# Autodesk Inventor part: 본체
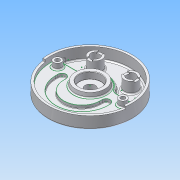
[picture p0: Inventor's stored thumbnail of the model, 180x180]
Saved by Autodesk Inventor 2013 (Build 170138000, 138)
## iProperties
Created: 2015-06
Part Number: 본체
Material: 알루미늄 6061
Document SubType Name: Modeling
Designer: Administrator
Density: 2.71 g/cm^3
Mass: 1340.45 g
Surface Area: 1046.04 cm^2
Volume: 494.633 cm^3
Author: Administrator
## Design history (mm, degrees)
sketch "스케치1"
  geometry: C1 r 95 at (0, 0); 1 further point
  constraints: 1 centre point, 1 coincident
  dimensions: "d0" = 190 diameter of C1
extrude "돌출1" new body sketch "스케치1" distance "d2" = 32.5; taper "d3" = 0 deg
sketch "스케치2"
  geometry: C1 r 95 at (0, 0) reference; C2 r 90 at (0, 0)
  constraints: 1 centre point, 1 coincident
  dimensions: "d4" = 180 diameter of C2
extrude "돌출2" cut sketch "스케치2" distance "d6" = 13; taper "d7" = 0 deg
sketch "스케치3"
  geometry: L1 (-95, 0)-(95, 0); L2 (0, 0)-(-94.075, -13.221); L3 (0, 0)-(94.075, -13.221); C1 r 90 at (0, 0) reference; A1 r 95 centre (0, 0) between (-95, 0) and (95, 0) reference
  constraints: 6 end point, 4 point on circle, 1 horizontal, 1 midpoint
  dimensions: "d8" = 8 deg angle of L1 L2; "d9" = 8 deg angle of L1 L3
extrude "돌출3" cut sketch "스케치3" distance "d10" = 5; taper "d11" = 0 deg
sketch "스케치4"
  geometry: C1 r 95 at (0, 0) reference; C2 r 26 at (0, 0)
  constraints: 1 centre point, 1 coincident
  dimensions: "d12" = 52 diameter of C2
extrude "돌출4" join sketch "스케치4" distance "d14" = 11.5; taper "d15" = -15 deg
sketch "스케치5"
  geometry: C1 r 90 at (0, 0) reference; C2 r 35 at (0, 0)
  constraints: 1 centre point, 1 coincident
  dimensions: "d16" = 70 diameter of C2
extrude "돌출5" join sketch "스케치5" distance "d18" = 10; taper "d19" = -10 deg
hole "구멍1" diameter "d22" = 23; stored, may be unused: countersink angle "d26" = 90 deg, drill point angle "d28" = 118 deg; dims "d20" = 10, "d21" = 10, "d23" = 6, "d24" = 50, "d25" = 15, "d27" = 8
sketch "스케치6"
  geometry: C1 r 35 at (0, 0) reference; C2 r 15 at (-40, 52); C3 r 15 at (40, 52)
  constraints: 2 centre point, 1 equal radius, 1 horizontal alignment
  dimensions: "d29" = 80 distance of C3.centre C2.centre; "d31" = 40 horizontal distance of C1.centre C2.centre; "d32" = 52 vertical distance of C3.centre C1.centre; "d33" = 30 diameter of C2
extrude "돌출6" join sketch "스케치6" stored distance "d34" = 10; taper "d35" = 0 deg
hole "구멍2" diameter "d38" = 20; stored, may be unused: countersink angle "d42" = 90 deg, drill point angle "d44" = 118 deg; dims "d36" = 10, "d37" = 10, "d39" = 6, "d40" = 20, "d41" = 15, "d43" = 8
hole "구멍3" diameter "d47" = 20; stored, may be unused: countersink angle "d51" = 90 deg, drill point angle "d53" = 118 deg; dims "d45" = 10, "d46" = 10, "d48" = 6, "d49" = 20, "d50" = 15, "d52" = 8
sketch "스케치7"
  geometry: L1 (-6, 13.748)-(-6, -13.748); L2 (6, 13.748)-(6, -13.748); L3 (66.252, 6)-(93.748, 6); L4 (93.748, -6)-(66.252, -6); C1 r 10 at (0, 0) reference; C2 r 10 at (80, 0) reference; A1 r 15 centre (0, 0) between (-6, 13.748) and (-6, -13.748) reference; A2 r 15 centre (80, 0) between (66.252, 6) and (93.748, 6) reference; 1 further point
  constraints: 8 end point, 8 point on circle, 2 parallel, 1 perpendicular, 1 vertical
  dimensions: "d54" = 12 distance between parallel lines of L2 L1; "d55" = 6 distance from line of C1.centre L1; "d56" = 12 distance between parallel lines of L4 L3; "d57" = 6 distance from line of L4 C2.centre
extrude "돌출7" cut sketch "스케치7" distance "d58" = 3; taper "d59" = 0 deg
sketch "스케치8"
  geometry: C1 r 35 at (0, 0) reference; C2 r 9 at (-74, 0); C3 r 9 at (74, 0)
  constraints: 2 centre point, 2 horizontal alignment, 1 equal radius
  dimensions: "d60" = 18 diameter of C2; "d62" = 148 distance of C3.centre C2.centre; "d63" = 74 distance of C1.centre C2.centre
extrude "돌출8" join sketch "스케치8" stored distance "d64" = 3; taper "d65" = 0 deg
sketch "스케치9"
  geometry: C1 r 9 at (-74, 0) reference; C2 r 9 at (74, 0) reference
hole "구멍4" sketch "스케치9" at (-74, 0), (74, 0) diameter "d66" = 10; stored, may be unused: countersink angle "d70" = 90 deg, drill point angle "d72" = 118 deg; dims "d67" = 6, "d68" = 18, "d69" = 11, "d71" = 8
sketch "스케치10"
  geometry: L1 (-90, -14)-(-88.904, -14); L2 (88.904, -14)-(90, -14); L3 (-59, -19)-(-59, -14); L4 (-41, -19)-(-41, -14); L5 (41, -19)-(41, -14); L6 (59, -19)-(59, -14); C1 r 35 at (0, 0) reference; A1 r 90 centre (0, 0) between (-88.904, -14) and (88.904, -14) reference; A2 r 59 centre (0, -19) between (-59, -19) and (59, -19); A3 r 41 centre (0, -19) between (-41, -19) and (41, -19); A4 r 9 centre (-50, -14) between (-41, -14) and (-59, -14); A5 r 9 centre (50, -14) between (59, -14) and (41, -14); 2 further points
  constraints: 12 end point, 10 point on circle, 8 tangent, 6 parallel, 4 centre point, 2 coincident, 1 perpendicular, 1 vertical, 1 vertical alignment
  dimensions: "d108" = 19 distance of point (0, -19) C1.centre; "d109" = 5 distance of L3.start L3.end; "d111" = 59 radius of A2; "d112" = 41 radius of A3
extrude "돌출9" cut sketch "스케치10" distance "d113" = 7; taper "d114" = 0 deg
sketch "스케치11"
  geometry: L1 (-90, 16)-(-38.833, 16); L2 (38.833, 16)-(90, 16); C1 r 9 at (-74, 0) reference; C2 r 9 at (74, 0) reference; C3 r 15 at (-40, 52) reference; C4 r 15 at (40, 52) reference; C5 r 90 at (0, 0) reference; A1 r 42 centre (0, 0) between (38.833, 16) and (-38.833, 16); A2 r 90 centre (0, 0) between (88.566, 16) and (-88.566, 16)
  constraints: 4 end point, 4 point on circle, 2 centre point, 2 coincident, 2 horizontal, 2 point on line, 1 collinear, 1 concentric
  dimensions: "d115" = 84 diameter of A1; "d118" = 16 distance from line of L1 C1.centre; "d119" = 16 distance from line of L2 C2.centre
extrude "돌출10" cut sketch "스케치11" distance "d120" = 12.5; taper "d121" = 0 deg
fillet "모깎기1" dims "d122" = 10
fillet "모깎기2" dims "d123" = 0.3
fillet "모깎기3" dims "d124" = 3
fillet "모깎기4" dims "d125" = 3
fillet "모깎기5" dims "d126" = 3
chamfer "모따기1" distance "d127" = 1; stored, may be unused: second distance "d128" = 2, angle "d129" = 45 deg
sketch "스케치12"
  geometry: C1 r 28.302 at (0, 0) reference; C2 r 68 at (0, 0)
  constraints: 1 centre point, 1 coincident, 1 other
  dimensions: "d130" = 136 diameter of C2
feature "엠보싱1" sketch "스케치12" dims "d133" = 0.5, "d134" = 0
fillet "모깎기6" dims "d135" = 1
fillet "모깎기7" dims "d136" = 3
fillet "모깎기8" dims "d137" = 3
sketch "스케치13"
  geometry: L1 (45.033, 13)-(75.657, 13) reference; L2 (-75.657, 13)-(-45.033, 13) reference; L3 (59, -14)-(59, -19) reference; L4 (-59, -19)-(-59, -14) reference; L5 (-41, -14)-(-41, -19) reference; L6 (41, -19)-(41, -14) reference; C1 r 12 at (-74, 0) reference; C2 r 12 at (74, 0) reference; C3 r 37.517 at (0, 0) reference; A1 r 13 centre (75.657, 26) between (75.657, 13) and (87.566, 20.788) reference; A2 r 13 centre (45.033, 26) between (33.775, 19.5) and (45.033, 13) reference; A3 r 39 centre (0, 0) between (33.775, 19.5) and (-33.775, 19.5) reference; A4 r 13 centre (-45.033, 26) between (-45.033, 13) and (-33.775, 19.5) reference; A5 r 13 centre (-75.657, 26) between (-87.566, 20.788) and (-75.657, 13) reference; A6 r 90 centre (0, 0) between (-87.566, 20.788) and (87.566, 20.788) reference; A7 r 59 centre (0, -19) between (-59, -19) and (59, -19) reference; A8 r 9 centre (-50, -14) between (-41, -14) and (-59, -14) reference; A9 r 41 centre (0, -19) between (-41, -19) and (41, -19) reference; A10 r 9 centre (50, -14) between (59, -14) and (41, -14) reference
node "솔리드1"
node "투영된 루프1"
other parameters: "d74" = 59, "d77" = 5, "d83" = 59, "d84" = 41, "d86" = 41, "d96" = 41, "d97" = 59, "d117" = 16
